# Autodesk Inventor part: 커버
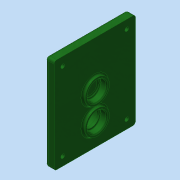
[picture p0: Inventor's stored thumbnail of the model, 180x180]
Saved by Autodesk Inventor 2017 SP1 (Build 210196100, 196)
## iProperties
Created: 2016-02
Part Number: 커버
Material: 알루미늄 6061
Document SubType Name: Modeling
Designer: mduedu
Density: 2.71 g/cm^3
Mass: 271.622 g
Surface Area: 265.357 cm^2
Volume: 100.23 cm^3
Appearance: 매끄러움 - 짙은 산림 녹색
Author: mduedu
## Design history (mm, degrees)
sketch "스케치1"
  geometry: L1 (63, 47)-(-47, 47); L2 (-47, 47)-(-47, -47); L3 (-47, -47)-(63, -47); L4 (63, -47)-(63, 47); 2 further points
  constraints: 8 end point, 2 parallel, 1 horizontal, 1 horizontal alignment, 1 midpoint, 1 perpendicular
  dimensions: "d102" = 94 distance of L3.end L1.start; "d104" = 47 distance from line of L2 point (0, 0); "d105" = 110 distance of L1.start L1.end
extrude "돌출1" new body sketch "스케치1" distance "d1" = 10; taper "d2" = 0 deg
sketch "스케치2"
  geometry: C1 r 14 at (0, 11); 1 further point
  constraints: 1 centre point, 1 vertical alignment
  dimensions: "d3" = 28 diameter of C1; "d6" = 11 distance of C1.centre point (0, 0)
extrude "돌출2" join sketch "스케치2" distance "d7" = 3; taper "d8" = 0 deg
sketch "스케치3"
  geometry: C1 r 14 at (0, -20); 1 further point
  constraints: 1 centre point, 1 vertical alignment
  dimensions: "d9" = 28 diameter of C1; "d10" = 20 distance of C1.centre point (0, 0)
extrude "돌출3" join sketch "스케치3" distance "d11" = 3; taper "d12" = 0 deg
hole "구멍1" diameter "d15" = 22; stored, may be unused: countersink angle "d19" = 90 deg, drill point angle "d21" = 0 deg; dims "d13" = 10, "d14" = 10, "d16" = 6, "d17" = 4, "d18" = 2, "d20" = 7
hole "구멍2" diameter "d24" = 18; stored, may be unused: countersink angle "d28" = 90 deg, drill point angle "d30" = 0 deg; dims "d22" = 10, "d23" = 10, "d25" = 6, "d26" = 4, "d27" = 2, "d29" = 1
hole "구멍3" diameter "d33" = 22; stored, may be unused: countersink angle "d37" = 90 deg, drill point angle "d39" = 0 deg; dims "d34" = 6, "d35" = 4, "d36" = 2, "d38" = 7, "d73" = 10, "d74" = 10
sketch "스케치4"
  geometry: C1 r 14 at (0, -20) reference; C2 r 18 at (0, -20); 1 further point
  constraints: 1 centre point, 1 coincident
  dimensions: "d40" = 36 diameter of C2
extrude "돌출4" join sketch "스케치4" distance "d41" = 4; taper "d42" = 0 deg
hole "구멍4" diameter "d45" = 22; stored, may be unused: countersink angle "d49" = 90 deg, drill point angle "d51" = 0 deg; dims "d43" = 10, "d44" = 10, "d46" = 6, "d47" = 4, "d48" = 2, "d50" = 7
hole "구멍5" diameter "d54" = 18; stored, may be unused: countersink angle "d58" = 90 deg, drill point angle "d60" = 0 deg; dims "d55" = 6, "d56" = 4, "d57" = 2, "d59" = 7, "d116" = 10, "d117" = 10
fillet "모깎기1" dims "d61" = 0.3
fillet "모깎기2" dims "d62" = 2
chamfer "모따기1" distance "d63" = 1; stored, may be unused: second distance "d64" = 2, angle "d65" = 45 deg
fillet "모깎기6" dims "d88" = 2
fillet "모깎기4" dims "d75" = 2
sketch "스케치9"
  geometry: L1 (47, 63)-(47, -47) reference; L2 (-47, 63)-(47, 63) reference; L3 (-47, -47)-(-47, 63) reference; L4 (47, -47)-(-47, -47) reference; L5 (37, 53)-(37, -37); L6 (37, -37)-(-37, -37); L7 (-37, -37)-(-37, 53); L8 (-37, 53)-(37, 53); C1 r 20 at (0, -20) reference; 5 further points
  constraints: 8 end point, 4 coincident, 3 other
  dimensions: "d107" = 10 distance between parallel lines of L8 L2
hole "구멍7" sketch "스케치9" at (-37, 53), (37, 53), (37, -37), (-37, -37) diameter "d108" = 4.5; stored, may be unused: countersink angle "d112" = 90 deg, drill point angle "d114" = 118 deg; dims "d109" = 6, "d110" = 8, "d111" = 4.6, "d113" = 8
fillet "모깎기8" dims "d106" = 3
fillet "모깎기9" dims "d115" = 3
node "솔리드1"
node "투영된 루프2"
